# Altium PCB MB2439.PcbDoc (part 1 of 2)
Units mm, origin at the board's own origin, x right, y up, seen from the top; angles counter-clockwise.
Board outline 43.1 x 47.12 mm, 4 copper layers (Top Layer, Internal 2, Internal 3, Bottom Layer), stack 1.565 mm thick; 79 components, 62 nets, 323 pads, 761 vias.
Unrouted connection lines stored in the file: 15.
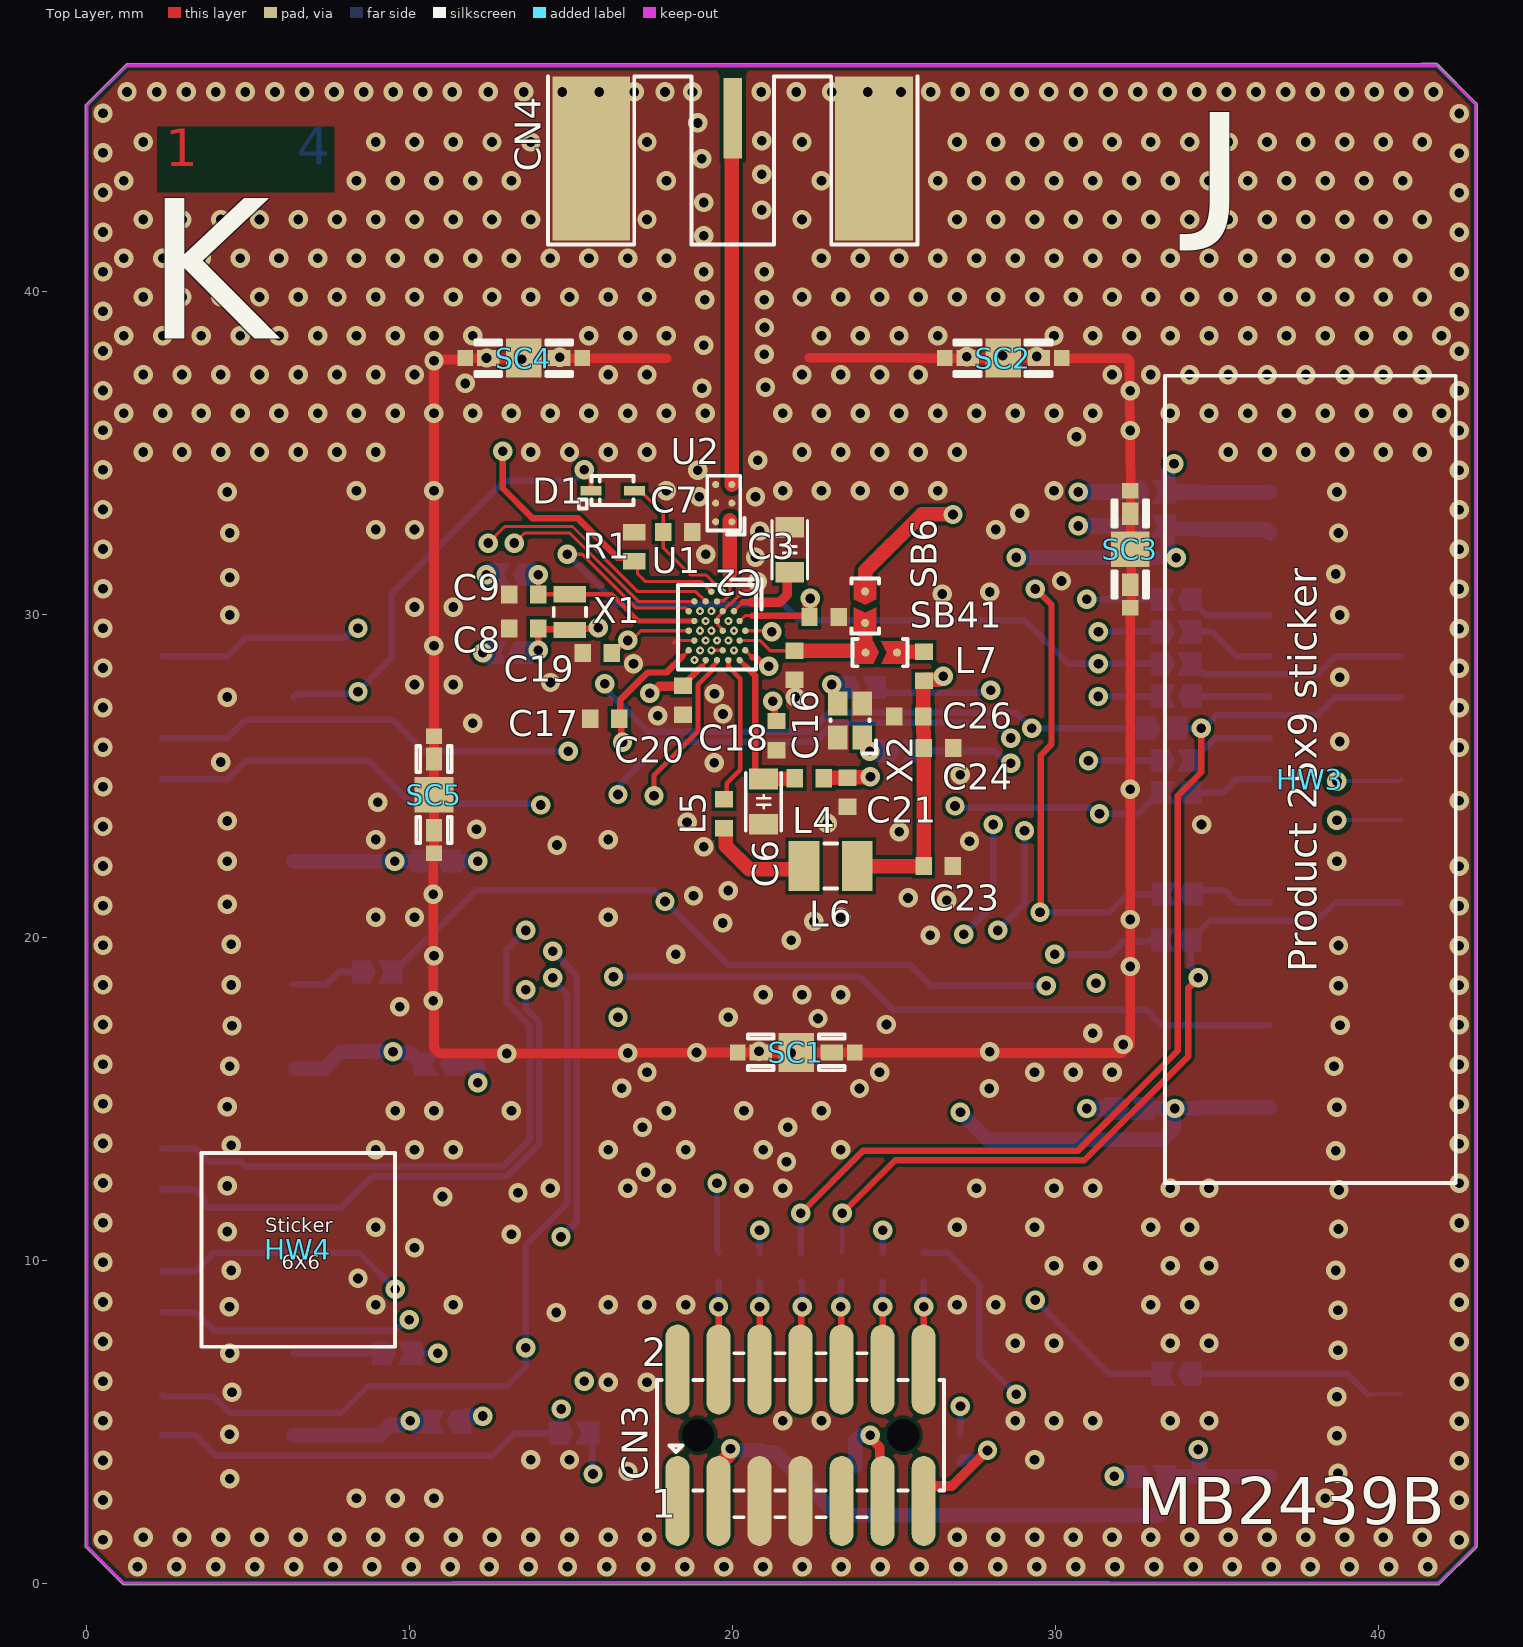
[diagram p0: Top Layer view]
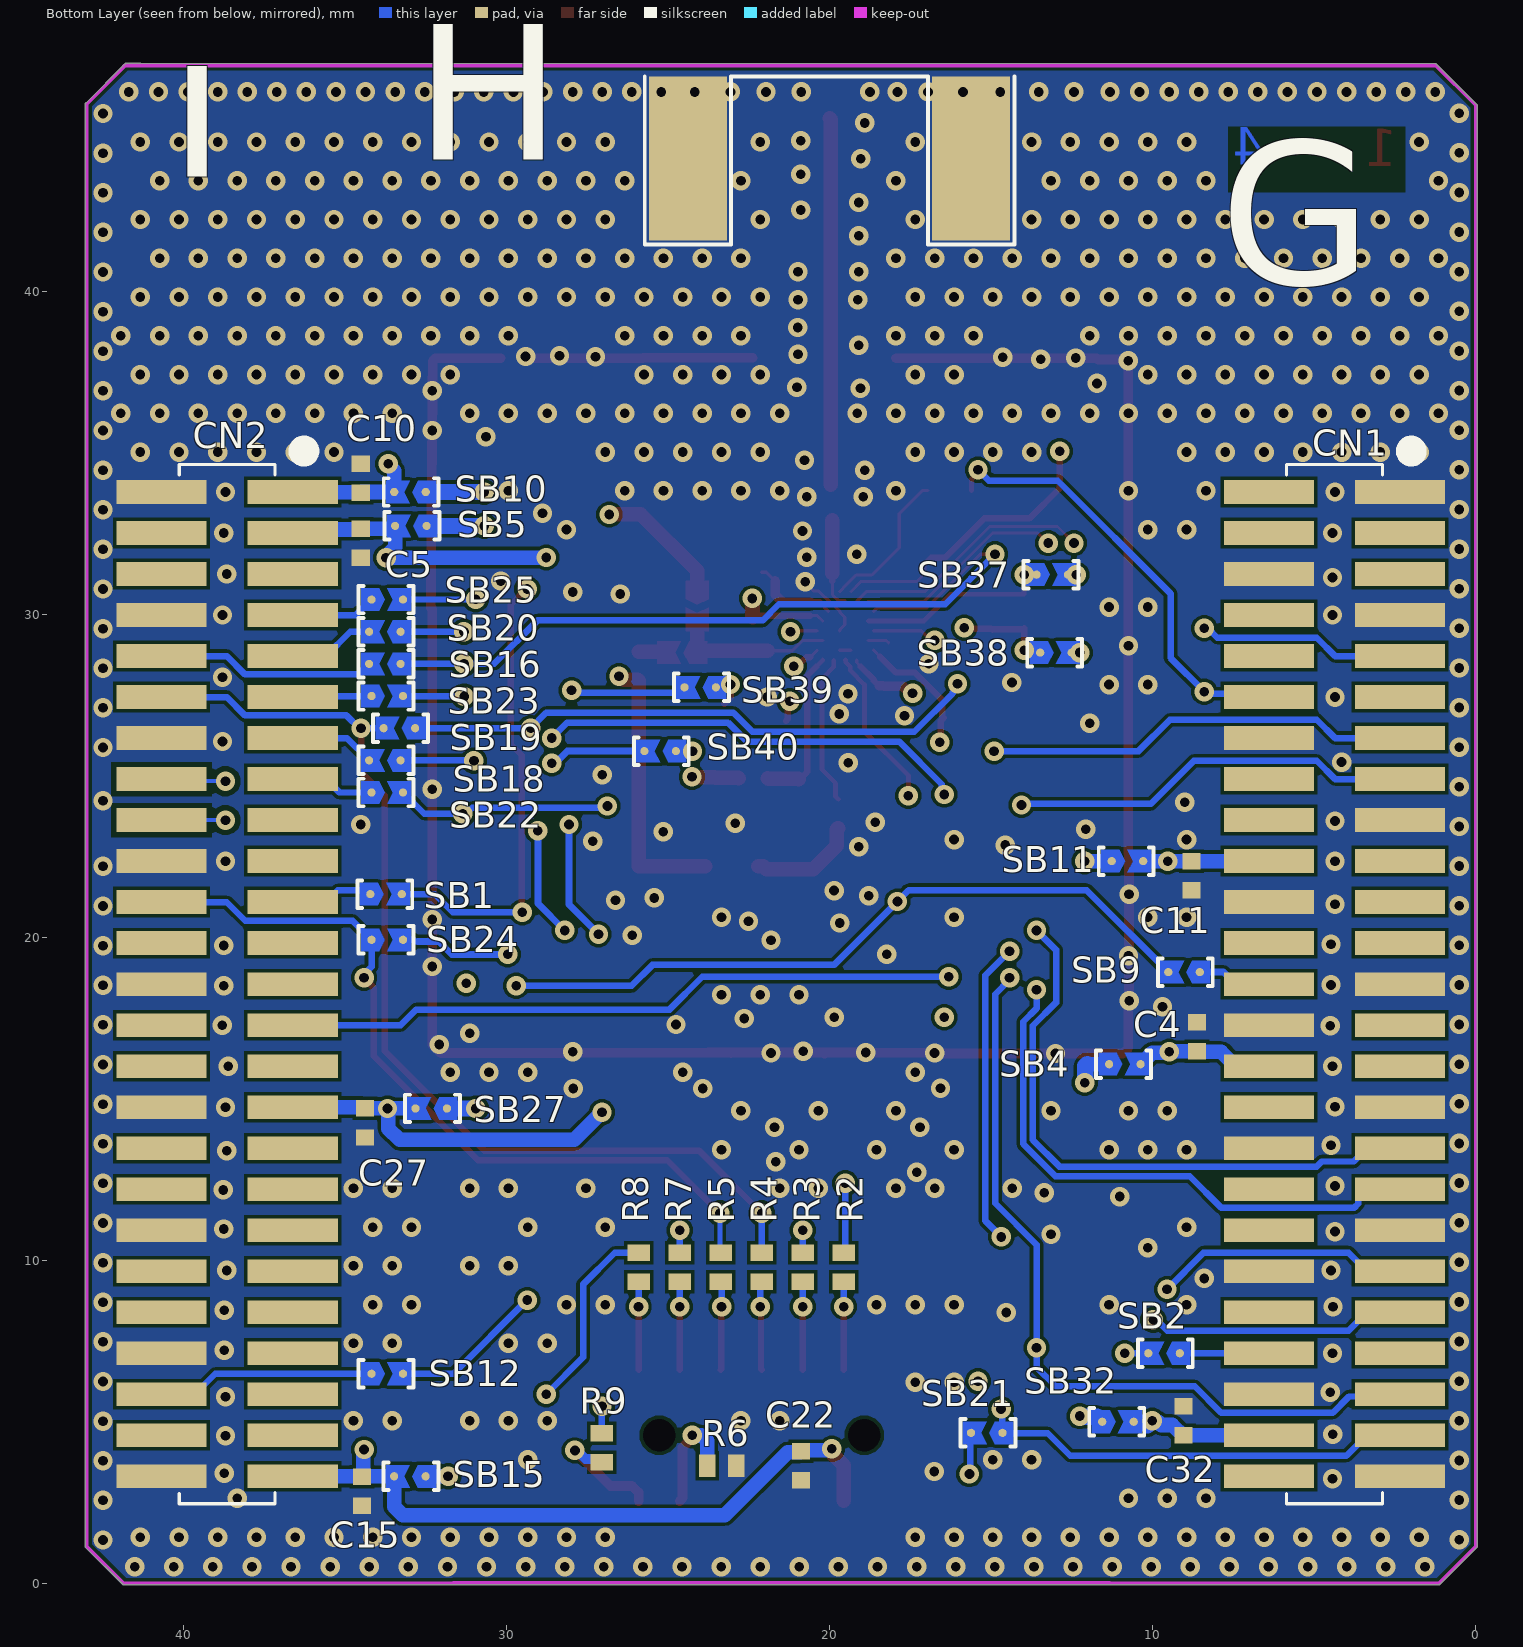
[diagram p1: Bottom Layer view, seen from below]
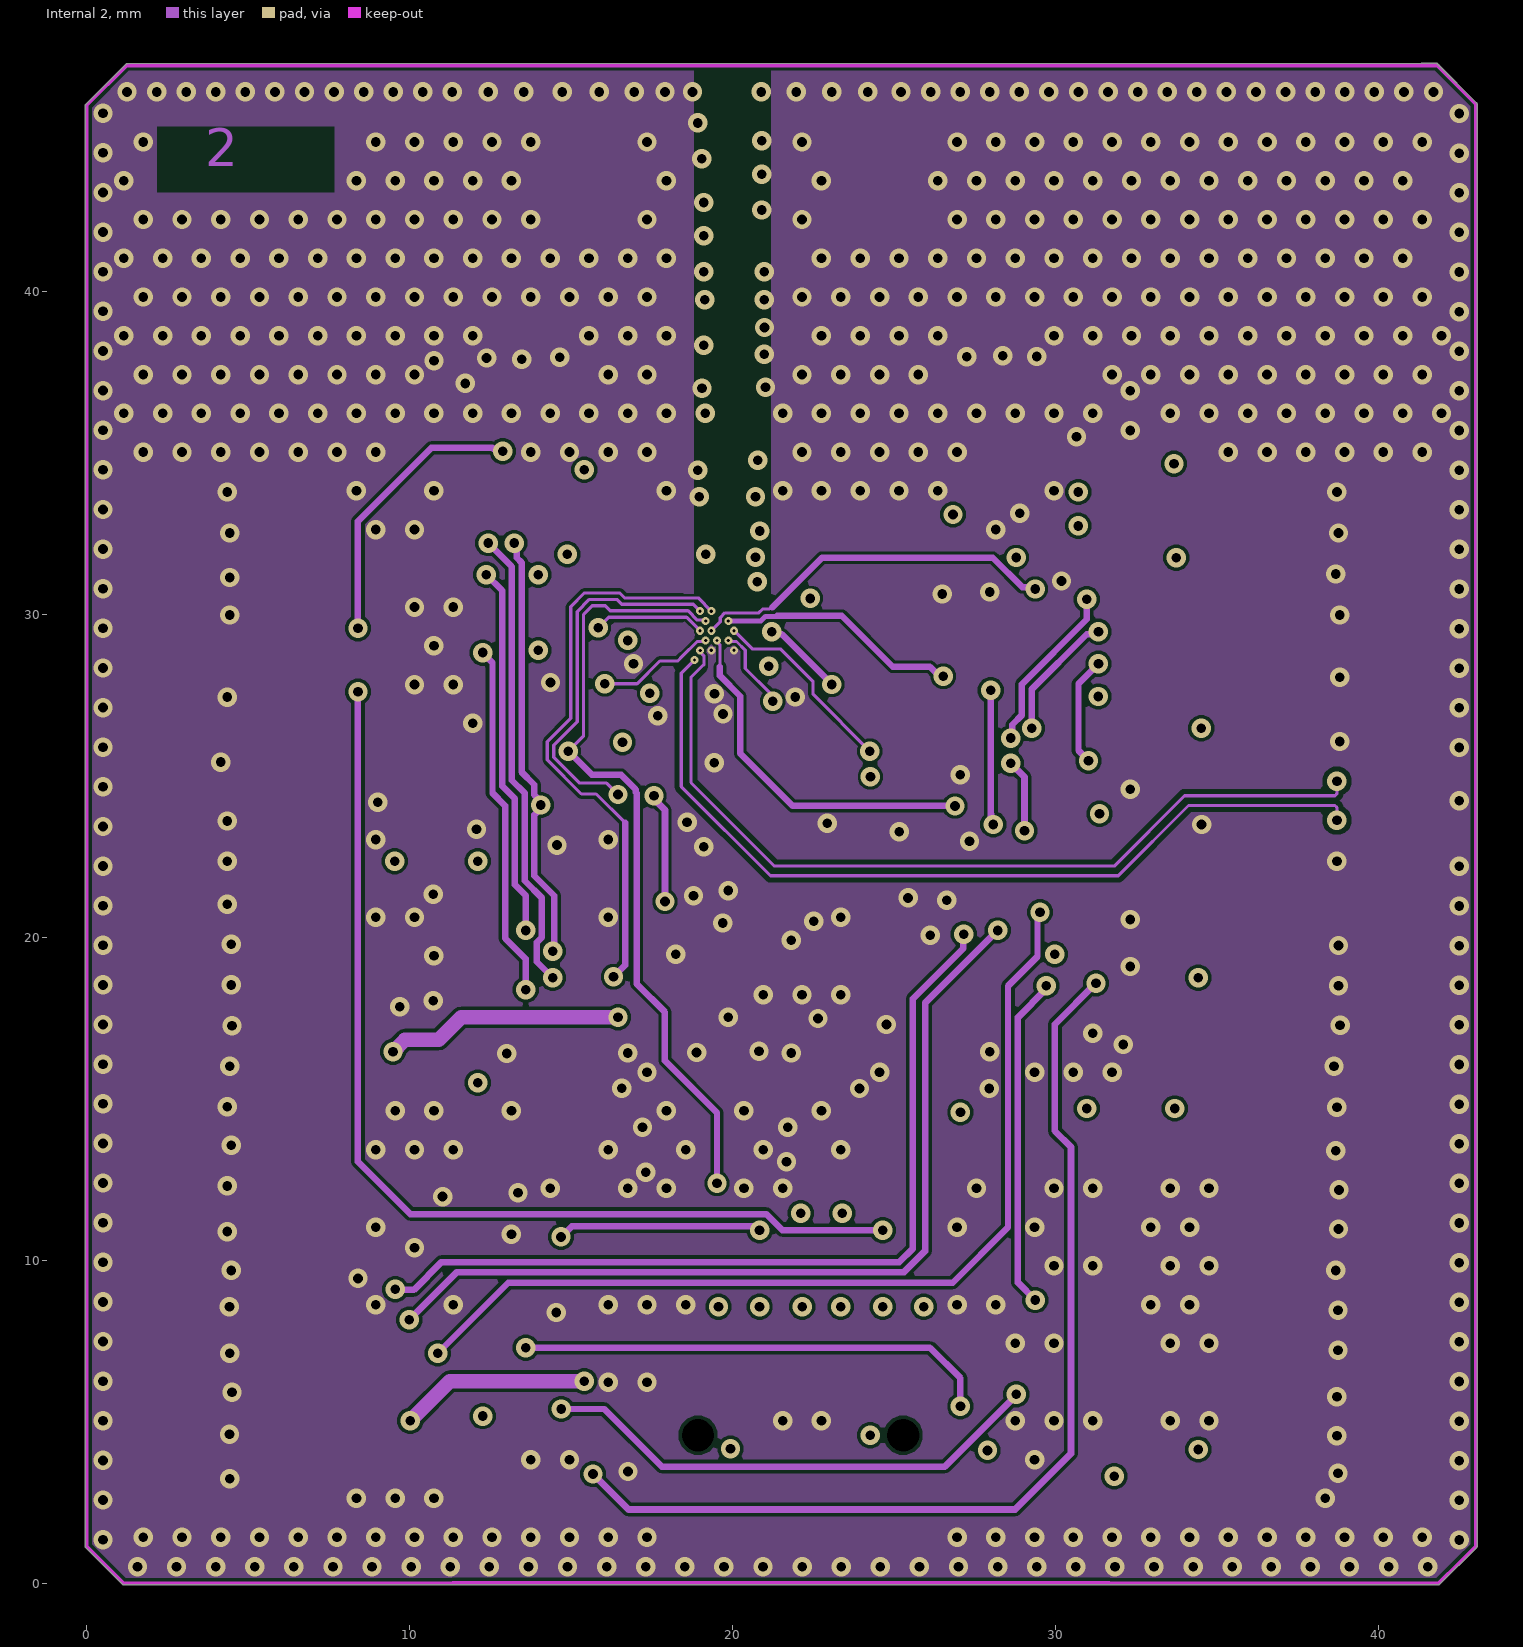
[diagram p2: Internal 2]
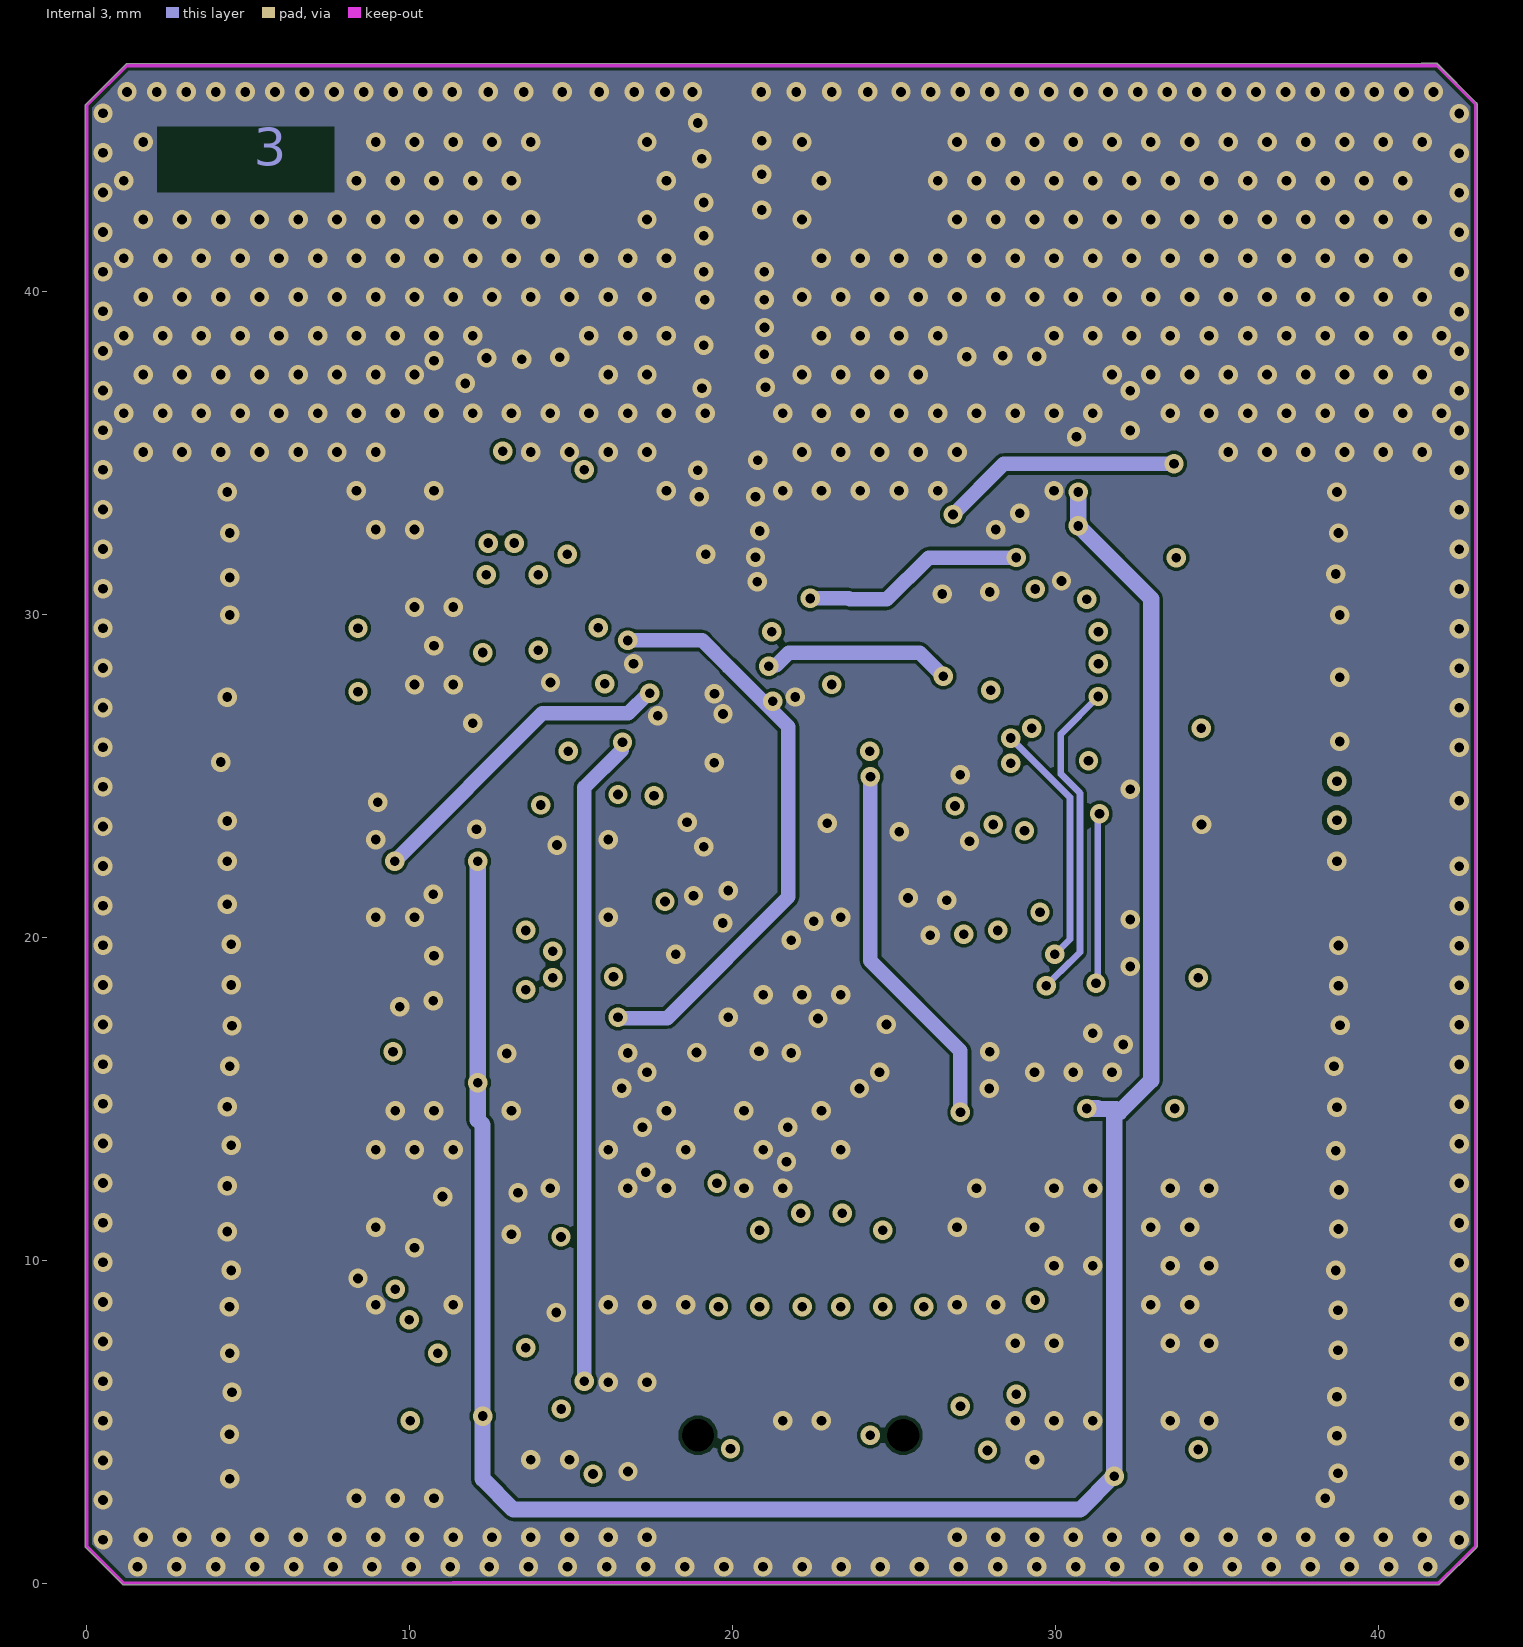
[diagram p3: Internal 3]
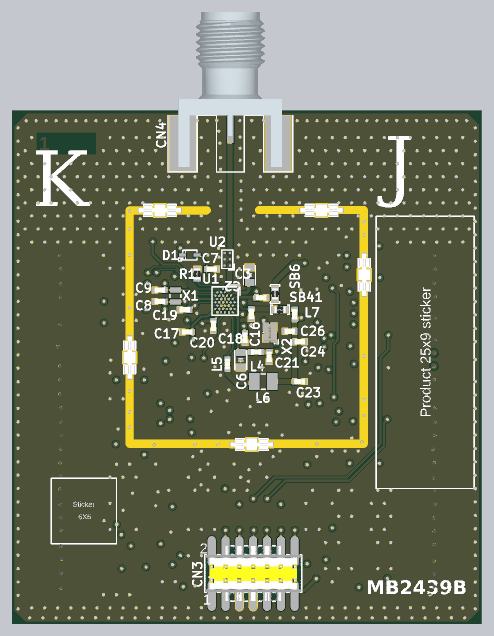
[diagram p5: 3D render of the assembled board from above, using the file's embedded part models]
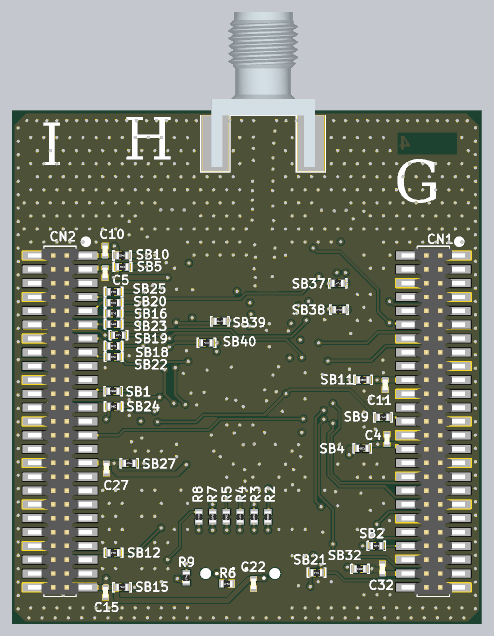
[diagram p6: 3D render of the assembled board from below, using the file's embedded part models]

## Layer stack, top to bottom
Top Solder: solder mask 0.0178, Solder Resist, Dk 4.2
Top Layer: signal copper 0.0406
Dielectric 1-2: core 0.0762, Prepreg, Dk 3.7
Internal 2: signal copper 0.0305
Dielectric 3: prepreg 1.27, Dk 4.5
Internal 3: signal copper 0.0305
Dielectric 3-4: core 0.0762, Prepreg, Dk 3.7
Bottom Layer: signal copper 0.0406
Board Layer Stack Bottom Solder: solder mask 0.0178, Solder Resist, Dk 4.2

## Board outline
-0.036,1.103 cw(c0,1.139) -0.05,1.139 -0.05,45.75 -0.05,45.755 cw(c0,45.755) -0.035,45.791 1.209,47.036 cw(c1.245,47) 1.245,47.05 41.326,47.066 41.78,47.066 cw(c41.78,47.015) 41.816,47.051 43.03,45.837 cw(c43.001,45.795) 43.051,45.795 cw(c43.002,45.795) 43.05,45.785 43.05,1.151 cw(c43.002,1.141) 43.051,1.141 cw(c43.001,1.141) 43.037,1.105 41.888,-0.036 cw(c41.852,0) 41.852,-0.05 1.139,-0.05 cw(c1.139,0) 1.103,-0.036

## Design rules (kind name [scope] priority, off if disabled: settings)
Clearance Clearance_CSP [WithinRoom('CSP')] p1: gap=0.075 ignorepadtopadclearanceinfootprint=FALSE
Clearance Clearance_DIFF90 [InNetClass('DIFF90')] p2: gap=0.16 ignorepadtopadclearanceinfootprint=FALSE
Clearance Clearance_IPD [WithinRoom('IPD')] p3: gap=0.1 ignorepadtopadclearanceinfootprint=FALSE
Clearance Clearance_RF [InNetClass('RF')] p4: gap=0.127 ignorepadtopadclearanceinfootprint=FALSE
Clearance [All] p5: gap=0.1 ignorepadtopadclearanceinfootprint=FALSE
ComponentClearance [All] p1: gap=0.1 collisioncheckmode=3 verticalgap=0.1 showdistances=FALSE
DiffPairsRouting [All] p1: maxlimit=0.2 minlimit=0.127 mostfreqgap=0.2 toplayer_mingap=0.2 toplayer_minwidth=0.1 toplayer_maxwidth=0.11 toplayer_prefwidth=0.11 midlayer1_mingap=0.2 midlayer1_minwidth=0.1 midlayer1_maxwidth=0.1 midlayer1_prefwidth=0.1 midlayer4_maxgap=0.127 midlayer4_prefgap=0.127 midlayer4_minwidth=0.05 midlayer4_maxwidth=0.14 midlayer4_prefwidth=0.072 bottomlayer_maxgap=0.127 bottomlayer_prefgap=0.127 bottomlayer_minwidth=0.127 bottomlayer_maxwidth=0.127 bottomlayer_prefwidth=0.127 impedanceprofiledriven=TRUE impedanceprofileid={FC601ECF-E89B-4FE3-84EC-BC5082A28B8A} impedanceprofilevalue=90.000000 maxuncoupledlength=12.7
HoleSize [All] p1: absolutevalues=TRUE maxlimit=10 minlimit=0.025 maxpercent=80.000 minpercent=20.000
HoleToHoleClearance [All] p1: gap=0.2 allowstackedmicrovias=TRUE
MatchedLengths "Schematic Matched Net Lengths" [InNetClass('DIFF90')] p1: tolerance=2 checknetsindiffpair=TRUE checkdiffpairvsdiffpair=FALSE checkxsignals=FALSE checkothers=FALSE
MaxMinImpedance "Schematic Impedance Constraint" [InNetClass('DIFF90')] p1: minimum=80.00 maximum=100.0
MinimumSolderMaskSliver [All] p1: minsoldermaskwidth=0.06
PlaneConnect [All] p1: planeconnectstyle=Relief reliefexpansion=0.508 reliefentries=4 reliefconductorwidth=0.21 reliefairgap=0.21
PolygonConnect PolygonConnect_1 [All vs IsNamedPolygon('GND_L01_P000')] p1: connectstyle=Direct reliefconductorwidth=0.254 reliefentries=4 polygonreliefangle="90 Angle" airgapwidth=0.254
PolygonConnect [All vs IsNamedPolygon('GND_L01_P000')] p2: connectstyle=Direct reliefconductorwidth=0.254 reliefentries=4 polygonreliefangle="90 Angle" airgapwidth=0.254
PolygonConnect Path_RF [InNet('NetC12_2')] p3: connectstyle=Direct reliefconductorwidth=0.254 reliefentries=4 polygonreliefangle="90 Angle" airgapwidth=0.254
PolygonConnect PolygonConnect_via [IsVia] p4: connectstyle=Direct reliefconductorwidth=0.254 reliefentries=4 polygonreliefangle="90 Angle" airgapwidth=0.254
PolygonConnect General [All] p5: connectstyle=Direct reliefconductorwidth=0.2 reliefentries=4 polygonreliefangle="90 Angle" airgapwidth=0.2
RoomDefinition IPD [False] p1: confinementstyle=ConfineIn formatcopy=TRUE lockcomponents=FALSE outline 19.338,34.239 20.416,34.239 20.416,32.754 19.338,32.754
RoomDefinition CSP [False] p2: confinementstyle=ConfineIn formatcopy=TRUE lockcomponents=FALSE outline 18.44,30.912 20.599,30.912 20.599,28.379 18.44,28.379
RoutingVias [All] p1: holewidth=0.3 width=0.8 viastyle="Through Hole" minholewidth=0.2 minwidth=0.5 maxholewidth=3.5 maxwidth=6.5
SilkToSilkClearance [All] p1: silktosilkclearance=0.2
SilkToSolderMaskClearance [IsPad] p1: minsilkscreentomaskgap=0.1 clearancetoexposedcopper=TRUE
SolderMaskExpansion [All] p1: expansion=0.102 istentingtop=FALSE
SupplyNets "Schematic Supply Nets_7" [InNet('VDD10')] p1: voltage=0.000
SupplyNets "Schematic Supply Nets_6" [InNet('VDD8')] p2: voltage=0.000
SupplyNets "Schematic Supply Nets_5" [InNet('GND')] p3: voltage=0.000
SupplyNets "Schematic Supply Nets_4" [InNet('VDD15')] p4: voltage=0.000
SupplyNets "Schematic Supply Nets_3" [InNet('VDDA')] p5: voltage=0.000
SupplyNets "Schematic Supply Nets_2" [InNet('VDD9')] p6: voltage=0.000
SupplyNets "Schematic Supply Nets_1" [InNet('VDD5')] p7: voltage=0.000
SupplyNets "Schematic Supply Nets" [InNet('VDD4')] p8: voltage=0.000
Width [All] p1: maxlimit=6 minlimit=0.1 preferedwidth=0.254 toplayer_prefwidth=0.15 midlayer1_maxwidth=0.512 midlayer1_prefwidth=0.15 midlayer4_minwidth=0.21 midlayer4_maxwidth=0.512 bottomlayer_prefwidth=0.15 minimp=50.000000 maximp=50.000000 favimp=50.000000
22 further rules are at their usual default settings.

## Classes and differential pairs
net class DIFF90: USB_FS_N USB_FS_P
differential pair class DIFF90: USB_FS
net class RF: NetCN4_1 NetU1_F2
component class "STM32 microcontroller I/Os & Clock": C4 C5 C7 C8 C9 C10 C11 C15 C27 C32 CN1 CN2 D1 R1 SB1 SB2 SB4 SB5 SB9 SB10 SB11 SB12 SB15 SB16 SB18 SB19 SB20 SB21 SB22 SB23 SB24 SB25 SB27 SB32 SB37 SB38 SB39 SB40 U1 X1 X2
component class "RF & Power Management Schematic": C2 C3 C6 C16 C17 C18 C19 C20 C21 C22 C23 C24 C26 CN3 CN4 HW1 L4 L5 L6 L7 R2 R3 R4 R5 R6 R7 R8 R9 SB6 SB41 SC1 SC2 SC3 SC4 SC5 U2
component class Project_Overview: HW2 HW3 HW4
differential pair USB_FS: +USB_FS_P -USB_FS_N

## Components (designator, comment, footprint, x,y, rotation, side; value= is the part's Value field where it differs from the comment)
C2 "Capacitor" C0603_H0P8 21.769,32.001 r270 top value=470nF
C3 "Capacitor" C0402 22.827,29.914 r0 top value=100nF
C4 "Capacitor" C0402 8.627,16.919 r270 bottom value=1uF
C5 "Capacitor" C0402 34.519,32.207 r90 bottom value=1uF
C6 "Capacitor" C0603_H0P8 20.955,24.2 r270 top value=10uF
C7 "Capacitor" C0402 18.297,32.546 r180 top value=100nF
C8 "Capacitor" C0402 13.529,29.567 r0 top value=6pF
C9 "Capacitor" C0402 13.529,30.62 r0 top value=6pF
C10 "Capacitor" C0402 34.519,34.211 r270 bottom value=1uF
C11 "Capacitor" C0402 8.788,21.907 r90 bottom value=1uF
C15 "Capacitor" C0402 34.478,2.845 r90 bottom value=1uF
C16 "Capacitor" C0402 21.919,28.425 r90 top value=100nF
C17 "Capacitor" C0402 16.039,26.766 r180 top value=100nF
C18 "Capacitor" C0402 21.351,26.247 r270 top value=100nF
C19 "Capacitor" C0402 15.811,28.804 r180 top value=100nF
C20 "Capacitor" C0402 18.455,27.337 r90 top value=1uF
C21 "Capacitor" C0402 23.559,24.496 r270 top value=1uF
C22 "Capacitor" C0402 20.887,3.631 r270 bottom value=1uF
C23 "Capacitor" C0402 26.359,22.205 r180 top value=4.7uF
C24 "Capacitor" C0402 26.372,25.864 r0 top value=100nF
C26 "Capacitor" C0402 25.455,26.834 r180 top value=100nF
C27 "Capacitor" C0402 34.392,14.249 r90 bottom value=1uF
C32 "Capacitor" C0402 9.044,5.027 r270 bottom value=1uF
CN1 "Header 25x2" FTSH-125-02-L-DV 4.366,18.548 r180 bottom locked
CN2 "Header 25x2" FTSH-125-02-L-DV 38.656,18.548 r180 bottom locked
CN3 "Header 7x2" CON_SAMTEC_FTSH-107-01-L-DV-K-A 22.101,4.579 r0 top locked
CN4 "SMA-J-P-H-ST-EM1" CON_SMA-RF_CINCH_142-0701-851 20,46.65 r0 top value=Jack_SMA_142-0701-851
D1 "SCHOTTKY_1A_2K" DIO_SOD523_1A_2K 16.281,33.831 r180 top value=BAT54KFILM
HW1 "Shield Cover" SHIELD_WURTH_36003200_21P8X21P8 90.373,17.78 r0 top value=36003200
HW3 "STICKER_PRODUCT" STICKER_PRODUCT_25X9 37.889,24.889 r90 top value="Sticker Product"
HW4 "STICKER_ES" STICKER_ES_6X6 6.547,10.321 r0 top value=N/A
L4 "BEAD" C0402 22.369,24.925 r180 top value="33R @ 100MHz"
L5 "Inductor" C0402 19.728,23.825 r270 top value=10nH
L6 "Inductor" IND_0805_MURATA_LQM21_H1P0 23.034,22.205 r0 top value=2.2uH
L7 "BEAD" C0402 25.917,28.395 r270 top value="33R @ 100MHz"
R1 "Resistor" R0402 16.954,32.096 r90 top value=100K
R2 "Resistor" R0402 19.561,9.779 r90 bottom value=47R
R3 "Resistor" R0402 20.832,9.779 r90 bottom value=47R
R4 "Resistor" R0402 22.103,9.779 r90 bottom value=47R
R5 "Resistor" R0402 23.374,9.779 r90 bottom value=47R
R6 "Resistor" R0402 23.345,3.631 r0 bottom value=47R
R7 "Resistor" R0402 24.646,9.779 r90 bottom value=47R
R8 "Resistor" R0402 25.917,9.779 r90 bottom value=47R
R9 "Resistor" R0402 27.051,4.191 r270 bottom value=47R
SB1 "SB_ON" SOLDER-BRIDGE_R0402-0R 33.773,21.336 r180 bottom
SB2 "SB_ON" SOLDER-BRIDGE_R0402-0R 9.606,7.118 r0 bottom
SB4 "SB_ON" SOLDER-BRIDGE_R0402-0R 10.897,16.07 r180 bottom
SB5 "SB_ON" SOLDER-BRIDGE_R0402-0R 32.931,32.738 r0 bottom
SB6 "SB_ON" SOLDER-BRIDGE_R0402-0R 24.101,30.259 r270 top
SB9 "SB_ON" SOLDER-BRIDGE_R0402-0R 8.988,18.921 r0 bottom
SB10 "SB_ON" SOLDER-BRIDGE_R0402-0R 32.959,33.788 r0 bottom
SB11 "SB_ON" SOLDER-BRIDGE_R0402-0R 10.816,22.358 r180 bottom
SB12 "SB_ON" SOLDER-BRIDGE_R0402-0R 33.736,6.483 r180 bottom
SB15 "SB_ON" SOLDER-BRIDGE_R0402-0R 32.961,3.308 r0 bottom
SB16 "SB_ON" SOLDER-BRIDGE_R0402-0R 33.736,28.466 r0 bottom
SB18 "SB_ON" SOLDER-BRIDGE_R0402-0R 33.736,25.479 r0 bottom
SB19 "SB_ON" SOLDER-BRIDGE_R0402-0R 33.286,26.474 r0 bottom
SB20 "SB_ON" SOLDER-BRIDGE_R0402-0R 33.736,29.461 r0 bottom
SB21 "SB_ON" SOLDER-BRIDGE_R0402-0R 15.097,4.654 r0 bottom
SB22 "SB_ON" SOLDER-BRIDGE_R0402-0R 33.736,24.483 r180 bottom
SB23 "SB_ON" SOLDER-BRIDGE_R0402-0R 33.736,27.47 r180 bottom
SB24 "SB_ON" SOLDER-BRIDGE_R0402-0R 33.736,19.921 r180 bottom
SB25 "SB_ON" SOLDER-BRIDGE_R0402-0R 33.736,30.457 r180 bottom
SB27 "SB_ON" SOLDER-BRIDGE_R0402-0R 32.3,14.699 r0 bottom
SB32 "SB_ON" SOLDER-BRIDGE_R0402-0R 11.109,4.998 r180 bottom
SB37 "SB_ON" SOLDER-BRIDGE_R0402-0R 13.143,31.228 r180 bottom
SB38 "SB_ON" SOLDER-BRIDGE_R0402-0R 13.03,28.816 r180 bottom
SB39 "SB_ON" SOLDER-BRIDGE_R0402-0R 23.971,27.74 r0 bottom
SB40 "SB_ON" SOLDER-BRIDGE_R0402-0R 25.211,25.765 r0 bottom
SB41 "SB_ON" SOLDER-BRIDGE_R0402-0R 24.563,28.816 r0 top
SC1 "Shield-clip_S0951-46R" CLIP_HARWIN_S0951-46R 21.968,16.434 r180 top locked value=S0951-46R
SC2 "Shield-clip_S0951-46R" CLIP_HARWIN_S0951-46R 28.372,37.934 r180 top locked value=S0951-46R
SC3 "Shield-clip_S0951-46R" CLIP_HARWIN_S0951-46R 32.309,32.021 r90 top locked value=S0951-46R
SC4 "Shield-clip_S0951-46R" CLIP_HARWIN_S0951-46R 13.529,37.934 r180 top locked value=S0951-46R
SC5 "Shield-clip_S0951-46R" CLIP_HARWIN_S0951-46R 10.75,24.42 r90 top locked value=S0951-46R
U1 "STM32WBA25HEF7" ICC_WLCSP37_2P61X2P41_P035 18.085,28.045 r0 top locked
U2 "IC_MLPF-WB-05D3" ICC_CSPG_6BUMPS_1X1P60_P050-P0577 19.722,33.443 r180 top value=MLPF-WB-05D3
X1 "XTAL_2_PINS" CRY_NX1610SE_2P 14.958,30.07 r270 top value=32.768kHz
X2 "XTAL_4_PINS" CRY_NX1612SA_4P 23.632,26.713 r90 top value=32MHz

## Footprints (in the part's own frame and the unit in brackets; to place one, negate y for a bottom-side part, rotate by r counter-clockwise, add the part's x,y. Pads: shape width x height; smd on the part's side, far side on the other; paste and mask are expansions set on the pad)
C0402 [mm]
  rect 0.51x0.56 smd mask+0.05: 1(-0.45,0) 2(0.45,0)
  body extent -0.5,-0.3 0.5,0.3, height 0.4
C0603_H0P8 [mm]
  rect 0.64x0.89 smd mask+0.05: 1(-0.7,0) 2(0.7,0)
  silkscreen extent -0.9,-0.55 0.9,0.55, body extent -0.9,-0.5 0.9,0.5, height 1
CLIP_HARWIN_S0951-46R [mm] "MCD-01587_CLIP-X1"
  rect 0.48x0.5 smd mask+0.1: 1(-1.81,0) 1(1.81,0)
  rect 0.7x0.5 smd mask+0.1: 1(-1.1,0) 1(1.1,0)
  rect 1.1x1.2 smd mask+0.1: 1(0,0)
  silkscreen extent -1.5,-0.55 1.5,0.55, body extent -2.05,-0.65 2.05,0.65, height 1.28
CON_SAMTEC_FTSH-107-01-L-DV-K-A [mm] "MCD-01959"
  oval 0.74x2.79 smd mask+0.05: 1(-3.81,-2.035) 2(-3.81,2.035) 3(-2.54,-2.035) 4(-2.54,2.035) 5(-1.27,-2.035) 6(-1.27,2.035) 7(0,-2.035) 8(0,2.035) 9(1.27,-2.035) 10(1.27,2.035) 11(2.54,-2.035) 12(2.54,2.035) 13(3.81,-2.035) 14(3.81,2.035)
  round 0 hole 1 unplated paste-2539.97 mask+0.05: NPTH1(-3.175,0) NPTH2(3.175,0)
  silkscreen extent -4.44,-2.54 4.44,2.54, body extent -4.44,-2.92 4.45,2.92, height 6.12
CON_SMA-RF_CINCH_142-0701-851 [mil] "MCD-02072"
  rect 22.83x98.43 smd mask+1.97: 1(0,-50.79)
  rect 95x200 smd mask+1.97: 2(172.48,-100) 3(-172.48,-100)
  rect 95x200 smd far side mask+1.97: 4(-172.48,-100) 5(172.48,-100)
  silkscreen extent -225,-205 225,0, body extent -189,-187 189,376, height 161
CRY_NX1610SE_2P [mm] "MCD-02291"
  rect 0.5x1 smd mask+0.05: 1(-0.55,0) 2(0.55,0)
  silkscreen extent -0.13,-0.5 0.13,0.5, body extent -0.8,-0.5 0.8,0.5, height 0.45
CRY_NX1612SA_4P [mm]
  rect 0.75x0.6 smd mask+0.038: 1(-0.525,-0.375) 2(0.525,-0.375) 3(0.525,0.375) 4(-0.525,0.375)
  silkscreen extent -1.02,-0.8 0.03,0.6, body extent -0.8,-0.6 0.8,0.6, height 0.51
DIO_SOD523_1A_2K [mm] "MCD-01677"
  rect 0.65x0.3 smd mask+0.05: 1(-0.675,0) 2(0.675,0)
  silkscreen extent -0.65,-0.45 1.05,0.55, body extent -0.85,-0.45 0.85,0.45, height 0.71
FTSH-125-02-L-DV [mil] "Header2x25 Reverse 1.27mm SAMTEC (FTSH-125-02-L-DV)"
  rect 110x29.02 smd: 1(80,600) 2(-80,600) 3(80,550) 4(-80,550) 5(80,500) 6(-80,500) 7(80,450) 8(-80,450) 9(80,400) 10(-80,400) 11(80,350) 12(-80,350) 13(80,300) 14(-80,300) 15(80,250) 16(-80,250) 17(80,200) 18(-80,200) 19(80,150) 20(-80,150) 21(80,100) 22(-80,100) 23(80,50) 24(-80,50) 25(80,0) 26(-80,0) 27(80,-50) 28(-80,-50) 29(80,-100) 30(-80,-100) 31(80,-150) 32(-80,-150) 33(80,-200) 34(-80,-200) 35(80,-250) 36(-80,-250) 37(80,-300) 38(-80,-300) 39(80,-350) 40(-80,-350) 41(80,-400) 42(-80,-400) 43(80,-450) 44(-80,-450) 45(80,-500) 46(-80,-500) 47(80,-550) 48(-80,-550) 49(80,-600) 50(-80,-600)
  silkscreen extent -58,-633 103,659, body extent -115,-625 115,625, height 190
ICC_CSPG_6BUMPS_1X1P60_P050-P0577 [mm] "MCD-03490"
  round 0.22 smd paste+0 mask+0: A1(-0.25,0.577) A2(-0.25,0) A3(-0.25,-0.577) B1(0.25,0.577) B2(0.25,0) B3(0.25,-0.577)
  silkscreen extent -0.64,-0.85 0.51,0.97, body extent -0.51,-0.81 0.51,0.81, height 0.7
ICC_WLCSP37_2P61X2P41_P035 [mm]
  round 0.2 smd paste+0 mask+0.038: A5(2.303,1.446) A7(2.303,0.84) B4(2.128,1.749) B6(2.128,1.143) B8(2.128,0.537) C3(1.953,2.052) C5(1.953,1.446) C7(1.953,0.84) D4(1.778,1.749) D6(1.778,1.143) D8(1.778,0.537) E1(1.603,2.658) E3(1.603,2.052) E5(1.603,1.446) E7(1.603,0.84) F2(1.428,2.355) F4(1.428,1.749) F6(1.428,1.143) F8(1.428,0.537) G1(1.253,2.658) G3(1.253,2.052) G5(1.253,1.446) G7(1.253,0.84) H2(1.078,2.355) H4(1.078,1.749) H6(1.078,1.143) H8(1.078,0.537) J3(0.903,2.052) J5(0.903,1.446) J7(0.903,0.84) K2(0.728,2.355) K4(0.728,1.749) K6(0.728,1.143) K8(0.728,0.537) L3(0.553,2.052) L5(0.553,1.446) L7(0.553,0.84)
  silkscreen extent 0.22,0.25 2.8,3.03, body extent 0.22,0.25 2.63,2.86, height 0.5
IND_0805_MURATA_LQM21_H1P0 [mm] "MCD-04691"
  rect 0.95x1.55 smd mask+0.05: 1(-0.825,0) 2(0.825,0)
  silkscreen extent -0.2,-0.7 0.2,0.7, body extent -1.07,-0.7 1.07,0.7, height 1
R0402 [mm]
  rect 0.51x0.7 smd mask+0.05: 1(-0.45,0) 2(0.45,0)
  body extent -0.52,-0.3 0.52,0.3, height 0.4
SHIELD_WURTH_36003200_21P8X21P8 [mm] "MCD-04686"
  silkscreen extent -10.95,-10.95 10.95,10.95, body extent -10.9,-10.9 10.9,10.9, height 2.3
SOLDER-BRIDGE_R0402-0R [mil] "MCD-01619"
  round 10 smd paste-393.7: 1(-17.72,0) 2(20.67,0)
  Top Layer region: 1.48,13.78 8.37,0 1.48,-13.78 30.51,-13.78 30.51,13.78
  Top Layer region: -30.51,-13.78 -30.51,13.78 -8.37,13.78 -1.48,0 -8.37,-13.78
  silkscreen extent -33,-17 33,17, body extent -20,-12 20,12, height 14
STICKER_ES_6X6 [mm] "Sticker to mention board QR code 8X8"
  silkscreen extent -3,-3 3,3
STICKER_PRODUCT_25X9 [mm] "Sticker to mention board CPN code"
  silkscreen extent -12.5,-4.5 12.5,4.5

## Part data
C2: library part MCD-01006, "Capacitor, MLCC, 470nF, 16V, X7R, +/-10%, 0603, T=0.8mm", Manufacturer=YAGEO, Manufacturer_Part_Number=CC0603KRX7R7BB474, Package=0603
C3 C7 C16 C17 C18 C19 C24 C26: library part MCD-00006, "Capacitor, MLCC, 100nF, 16V, X7R, +/-10%, 0402, T=0.5mm", Manufacturer=YAGEO, Manufacturer_Part_Number=CC0402KRX7R7BB104, Package=0402
C4 C5 C10 C11 C15 C20 C21 C22 C27 C32: library part MCD-01722, "Capacitor, MLCC, 1uF, 10V, X5R, +/-10%, 0402, T=0.5mm", Manufacturer=YAGEO, Manufacturer_Part_Number=CC0402KRX5R6BB105, Package=0402
C6: library part MCD-02733, "Capacitor, MLCC, 10uF, 10V, X6S, +/-20%, 0603, T=1mm", Manufacturer=MURATA, Manufacturer_Part_Number=GRM188C81A106MA73, Package=0603
C8 C9: library part MCD-03185, "Capacitor, MLCC, 6pF, 50V, C0G/NP0, +/-0,25pF, 0402, T=0.5mm", Manufacturer=MURATA, Manufacturer_Part_Number=GJM1555C1H6R0CB01, Package=0402
C23: library part MCD-01356, "Capacitor, MLCC, 4.7uF, 6V3, X5R, 20%, 0402, T=0.5mm", Manufacturer=MURATA, Manufacturer_Part_Number=GRM155R60J475ME47, Package=0402
CN1 CN2: library part MCD-02746, "Header, 25x2, 1.27mm, VR, SMD, T=4.83mm", Manufacturer=SAMTEC, Manufacturer_Part_Number=FTSH-125-02-L-DV
CN3: library part MCD-01531, "Header, 7x2, 1.27mm, VR, T=5.97mm, FTSH series STDC14 without Alignment Pin", Manufacturer=SAMTEC, Manufacturer_Part_Number=FTSH-107-01-L-DV-K
CN4: library part MCD-02072, "Jack_SMA, VR, PCB edge, 50R, T=7.92mm", Manufacturer=CINCH, Manufacturer_Part_Number=142-0701-851
D1: library part MCD-01677, "Diode, Schottky, 0V9, 100mA, 40V, SOD-523", Manufacturer=STMICROELECTRONICS, Manufacturer_HQ_COO=EU, Manufacturer_Part_Number=BAT54KFILM, Package=SOD-523
HW1: library part MCD-04686, "RF Shield cover, 21.5x21.5x3.3mm", Manufacturer="WURTH ELEKTRONIK", Manufacturer_Part_Number=36003200
HW3: library part MCD-00547, "Sticker product, 25x9mm", Manufacturer=N/A, Manufacturer_HQ_COO=Unknown
HW4: library part MCD-00234, "Sticker ES, 6x6mm", Manufacturer=N/A
L4 L7: library part MCD-04372, "Ferrite bead, 33R @ 100MHz, 3A, 22mR, 0402, T=0.5mm", Manufacturer=MURATA, Manufacturer_Part_Number=BLM15PX330SN1, Package=0402
L5: library part MCD-03035, "Inductor, 10nH, +/-2%, 0.5A, 260mR, 0402, T=0.5mm", Manufacturer=MURATA, Manufacturer_Part_Number=LQG15HS10NJ02D, Package=0402
L6: library part MCD-04691, "Inductor, 2.2uH, +/-30%, 0.6A, 0R23, 0805, T=0.9mm", Manufacturer=MURATA, Manufacturer_Part_Number=LQM21PN2R2NGC, Package=0805
R1: library part MCD-00059, "Resistor, 100K, 0402, +/-1%, 1/16W", Manufacturer=YAGEO, Manufacturer_Part_Number=RC0402FR-07100KL, Package=0402
R2 R3 R4 R5 R6 R7 R8 R9: library part MCD-00481, "Resistor, 47R, 0402, +/-1%, 1/16W", Manufacturer=YAGEO, Manufacturer_Part_Number=RC0402FR-0747RL, Package=0402
SB1 SB2 SB4 SB5 SB6 SB9 SB10 SB11 SB12 SB15 SB16 SB18 SB19 SB20 SB21 SB22 SB23 SB24 SB25 SB27 SB32 SB37 SB38 SB39 SB40 SB41: library part MCD-01618, "Resistor, 0R, SB0402, 5%, 0.063W", Manufacturer=YAGEO, Manufacturer_Part_Number=RC0402JR-070RL, Package=0402
SC1 SC2 SC3 SC4 SC5: library part MCD-01587, "shield clip Harwin S0951-46R to fix RF shielded cavity", Manufacturer=HARWIN, Manufacturer_Part_Number=S0951-46R
U1: library part MCD-04938, "MCU, ARM Cortex-M33 32-bit, 512KB Flash, 96KB RAM, Crypto", Manufacturer=STMICROELECTRONICS, Package=WLCSP37
U2: library part MCD-05125, "IC, 2.4GHz low pass filter matched to WBA CSP package mini board", Manufacturer=STMICROELECTRONICS, Manufacturer_Part_Number=MLPF-WB-05D3, Package=CSP6
X1: library part MCD-02579, "Crystal, 32.768kHz, 6pF, +/-20ppm, 70KR, 1.6x1mm", Manufacturer=NDK, Manufacturer_Part_Number=NX1610SE-32.768KHz-EXS00A-MU01501, Package=1.6x1.0mm
X2: library part MCD-02578, "Crystal, 32MHz, 8pF, +/-10ppm, 40R, 1612(metric)", Manufacturer=NDK, Manufacturer_Part_Number=NX1612SA-32MHz-EXS00A-CS09166, Package=1612(metric)

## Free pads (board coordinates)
  round 0.508 on Mech16: 1(-2.772,-77.554) 1(46.075,-77.554)

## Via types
v1: diameter 0.6, hole 0.3, Top Layer to Bottom Layer, tented both sides, 747 vias
v2: diameter 0.25, hole 0.1, Top Layer to Internal 2, 14 vias

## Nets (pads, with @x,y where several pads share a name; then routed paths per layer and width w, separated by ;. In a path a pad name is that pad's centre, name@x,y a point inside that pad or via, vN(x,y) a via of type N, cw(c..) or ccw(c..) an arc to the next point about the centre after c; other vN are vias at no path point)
GND: C2.1 C3.2 C4.1 C5.1 C6.2 C7.1 C8.1 C9.1 C10.1 C11.1 C15.1 C16.1 C17.2 C18.2 C19.2 C20.1 C21.2 C22.2 C23.1 C24.2 C26.2 C27.1 C32.1 CN1.1 CN1.6 CN1.7 CN1.14 CN1.17 CN1.22 CN1.25 CN1.28 CN1.31 CN1.34 CN1.37 CN1.40 CN1.46 CN1.49 CN2.2 CN2.8 CN2.14 CN2.20 CN2.26 CN2.32 CN2.38 CN2.44 CN2.50 CN3.5 CN3.7 CN4.2 CN4.3 CN4.4 CN4.5 R1.2 R6.1 SC1.1 SC2.1 SC3.1 SC4.1 SC5.1 U1.C7 U1.E3 U1.E5 U1.E7 U1.F4 U1.G7 U1.K6 U2.A2 U2.B1 U2.B2 U2.B3 X2.2 X2.4 | length 83.8
  Top Layer w0.1: 18.175,29.117 18.246,29.188 U1.K6@18.813,29.188 ; v2(19.338,28.885) U1.E7@19.688,28.885 ; U1.E5@19.688,29.491 19.688,29.518 19.532,29.674 19.532,29.775 U1.F4@19.513,29.794 19.532,29.813 19.532,29.914 19.688,30.07 U1.E3@19.688,30.097 19.913,30.322 19.937,30.322 20.335,30.72 20.492,30.72 20.599,30.827 20.605,30.833 20.605,30.844 v1@20.604,30.846
  Top Layer w0.3: v1(10.724,18.039) 10.75,18.013 10.75,16.576 10.926,16.4 16.733,16.4 v1(16.751,16.417) 16.759,16.426 18.856,16.426 18.864,16.417 18.88,16.434 20.124,16.434 20.158,16.4 20.192,16.434 SC1.1@20.868,16.434 20.885,16.417 20.902,16.434 SC1.1@21.816,16.434 ; v1@10.728,18.043 10.728,22.587 SC5.1@10.75,22.61 SC5.1@10.75,23.32 SC5.1@10.75,24.42 SC5.1@10.75,25.52 SC5.1@10.75,26.23 v1(10.75,37.853) 10.79,37.894 11.678,37.894 SC4.1@11.719,37.934 SC4.1@12.429,37.934 SC4.1@13.529,37.934 SC4.1@14.629,37.934 SC4.1@15.339,37.934 17.951,37.934 ; v1(21.816,16.417) 21.952,16.417 SC1.1@21.968,16.434 23.034,16.434 23.051,16.417 SC1.1@23.068,16.434 ; 22.377,37.948 25.781,37.948 25.795,37.934 SC2.1@26.562,37.934 SC2.1@27.272,37.934 SC2.1@28.372,37.934 SC2.1@29.472,37.934 ; SC1.1@23.068,16.434 SC1.1@23.778,16.434 23.786,16.426 28.255,16.426 28.263,16.417 32.045,16.417 32.309,16.681 v1(32.309,19.096) v1(32.309,24.583) 32.309,30.171 32.349,30.211 32.343,30.921 32.34,31.369 32.34,31.394 32.335,32.021 32.326,33.121 32.32,33.831 32.296,36.919 32.296,36.935 32.289,37.853 32.208,37.934 SC2.1@30.182,37.934
  other v1: 1.567,0.508 2.778,0.508 3.988,0.508 5.199,0.508 6.41,0.508 7.621,0.508 8.831,0.508 10.042,0.508 11.253,0.508 12.463,0.508 13.674,0.508 14.885,0.508 16.096,0.508 17.306,0.508 18.517,0.508 19.728,0.508 20.939,0.508 22.149,0.508 23.36,0.508 24.571,0.508 25.782,0.508 26.992,0.508 28.203,0.508 29.414,0.508 30.624,0.508 31.835,0.508 33.046,0.508 34.257,0.508 35.467,0.508 36.678,0.508 37.889,0.508 39.1,0.508 40.31,0.508 41.521,0.508 0.5,1.346 42.5,1.337 1.747,1.425 2.947,1.425 4.147,1.425 5.347,1.425 6.547,1.425 7.747,1.425 8.947,1.425 10.147,1.425 11.347,1.425 12.547,1.425 13.747,1.425 14.947,1.425 16.147,1.425 17.347,1.425 26.947,1.425 28.147,1.425 29.347,1.425 30.547,1.425 31.747,1.425 32.947,1.425 34.147,1.425 35.347,1.425 36.547,1.425 37.747,1.425 38.947,1.425 40.147,1.425 41.347,1.425 42.5,2.564 0.5,2.573 8.347,2.625 9.547,2.625 10.747,2.625 38.347,2.625 4.428,3.234 38.742,3.406 16.759,3.458 0.5,3.8 42.5,3.791 13.747,3.825 14.947,3.825 29.347,3.825 38.71,4.567 4.416,4.609 0.5,5.027 21.547,5.025 22.747,5.025 28.747,5.025 29.947,5.025 31.147,5.025 33.547,5.025 34.747,5.025 42.5,5.018 38.71,5.769 4.494,5.907 16.147,6.225 17.347,6.225 42.5,6.245 0.5,6.254 4.428,7.118 38.742,7.214 28.747,7.425 29.947,7.425 33.547,7.425 34.747,7.425 0.5,7.481 42.5,7.472 14.534,8.382 38.742,8.447 4.414,8.563 8.947,8.625 11.347,8.625 16.147,8.625 17.347,8.625 18.547,8.625 26.947,8.625 28.147,8.625 32.947,8.625 34.147,8.625 0.5,8.708 42.5,8.699 8.395,9.437 4.475,9.684 38.673,9.684 29.947,9.825 31.147,9.825 33.547,9.825 34.747,9.825 42.5,9.926 0.5,9.935 10.147,10.382 13.147,10.801 4.35,10.887 38.757,10.965 8.947,11.025 26.947,11.025 29.347,11.025 32.947,11.025 34.147,11.025 0.5,11.162 42.5,11.153 11.015,11.97 13.351,12.092 38.774,12.176 14.347,12.225 16.747,12.225 17.947,12.225 20.347,12.225 21.547,12.225 27.547,12.225 29.947,12.225 31.147,12.225 33.547,12.225 34.747,12.225 4.35,12.3 0.5,12.389 42.5,12.38 17.306,12.728 21.665,13.049 38.673,13.39 8.947,13.425 10.147,13.425 11.347,13.425 16.147,13.425 18.547,13.425 20.947,13.425 23.347,13.425 4.475,13.557 42.5,13.607 0.5,13.616 17.205,14.116 21.707,14.116 9.547,14.625 10.747,14.625 13.147,14.625 17.947,14.625 20.347,14.625 22.747,14.625 4.35,14.756 38.71,14.738 42.5,14.834 0.5,14.843 23.925,15.316 27.94,15.316 16.566,15.32 17.347,15.825 24.547,15.825 29.347,15.825 30.547,15.825 31.747,15.825 4.428,16.008 38.618,16.008 0.5,16.07 42.5,16.061 13.007,16.4 18.881,16.434 27.96,16.459 20.813,16.469 32.089,16.679 31.147,17.025 4.494,17.257 38.807,17.272 0.5,17.297 24.759,17.297 42.5,17.288 22.642,17.485 19.857,17.524 9.694,17.849 20.947,18.225 22.147,18.225 23.347,18.225 38.757,18.498 42.5,18.515 0.5,18.524 4.475,18.524 10.747,19.425 18.233,19.47 0.5,19.751 38.757,19.746 42.5,19.742 4.475,19.789 21.816,19.911 26.115,20.061 19.688,20.443 22.513,20.496 32.309,20.551 8.947,20.625 10.147,20.625 16.147,20.625 23.347,20.625 0.5,20.978 42.5,20.969 4.35,21.027 26.63,21.15 25.43,21.218 18.787,21.286 10.728,21.333 19.863,21.446 42.5,22.196 0.5,22.205 4.35,22.357 38.71,22.358 19.1,22.8 14.559,22.855 27.332,22.973 8.947,23.025 16.147,23.025 25.156,23.267 12.066,23.343 0.5,23.432 34.519,23.494 22.927,23.532 18.587,23.563 4.35,23.6 9.005,24.176 42.5,24.225 0.5,24.659 27.043,25.034 4.147,25.425 19.428,25.402 42.5,25.877 0.5,25.886 38.801,26.061 11.947,26.625 17.683,26.861 19.698,26.916 0.5,27.113 42.5,27.104 4.35,27.438 21.933,27.44 19.433,27.536 10.147,27.825 11.347,27.825 14.356,27.888 38.801,28.048 0.5,28.34 42.5,28.331 16.929,28.468 10.747,29.025 42.5,29.558 0.5,29.567 4.428,29.978 38.801,29.978 10.147,30.225 11.347,30.225 26.486,30.631 27.96,30.69 42.5,30.785 0.5,30.794 20.757,31.009 30.182,31.031 4.428,31.14 38.673,31.248 20.706,31.771 19.163,31.858 0.5,32.021 42.5,32.012 4.428,32.518 38.757,32.518 20.839,32.58 8.947,32.625 10.147,32.625 28.147,32.625 28.891,33.128 0.5,33.248 42.5,33.239 18.961,33.64 20.706,33.64 4.35,33.788 38.71,33.788 8.347,33.825 10.747,33.825 17.947,33.825 21.547,33.825 22.747,33.825 23.947,33.825 25.147,33.825 26.347,33.825 29.947,33.825 18.917,34.466 42.5,34.466 0.5,34.475 20.777,34.773 1.747,35.025 2.947,35.025 4.147,35.025 5.347,35.025 6.547,35.025 7.747,35.025 8.947,35.025 13.747,35.025 14.947,35.025 16.147,35.025 17.347,35.025 22.147,35.025 23.347,35.025 24.547,35.025 25.747,35.025 26.947,35.025 35.347,35.025 36.547,35.025 37.747,35.025 38.947,35.025 40.147,35.025 41.347,35.025 30.643,35.495 0.5,35.702 32.306,35.693 42.5,35.693 1.147,36.225 2.347,36.225 3.547,36.225 4.747,36.225 5.947,36.225 7.147,36.225 8.347,36.225 9.547,36.225 10.747,36.225 11.947,36.225 13.147,36.225 14.347,36.225 15.547,36.225 16.747,36.225 17.947,36.225 19.147,36.225 21.547,36.225 22.747,36.225 23.947,36.225 25.147,36.225 26.347,36.225 27.547,36.225 28.747,36.225 29.947,36.225 31.147,36.225 33.547,36.225 34.747,36.225 35.947,36.225 37.147,36.225 38.347,36.225 39.547,36.225 40.747,36.225 41.947,36.225 0.5,36.929 32.309,36.92 42.5,36.92 19.047,37.001 21.013,37.028 11.722,37.151 1.747,37.425 2.947,37.425 4.147,37.425 5.347,37.425 6.547,37.425 7.747,37.425 8.947,37.425 10.147,37.425 16.147,37.425 17.347,37.425 22.147,37.425 23.347,37.425 24.547,37.425 25.747,37.425 31.747,37.425 32.947,37.425 34.147,37.425 35.347,37.425 36.547,37.425 37.747,37.425 38.947,37.425 40.147,37.425 41.347,37.425 13.464,37.896 12.378,37.94 14.639,37.96 27.249,37.975 29.416,37.983 28.365,38.003 20.979,38.049 42.5,38.147 0.5,38.156 19.1,38.335 1.147,38.625 2.347,38.625 3.547,38.625 4.747,38.625 5.947,38.625 7.147,38.625 8.347,38.625 9.547,38.625 10.747,38.625 11.947,38.625 15.547,38.625 16.747,38.625 17.947,38.625 22.747,38.625 23.947,38.625 25.147,38.625 26.347,38.625 29.947,38.625 31.147,38.625 32.347,38.625 33.547,38.625 34.747,38.625 35.947,38.625 37.147,38.625 38.347,38.625 39.547,38.625 40.747,38.625 41.947,38.625 20.985,38.884 0.5,39.383 42.5,39.374 19.129,39.74 20.979,39.74 1.747,39.825 2.947,39.825 4.147,39.825 5.347,39.825 6.547,39.825 7.747,39.825 8.947,39.825 10.147,39.825 11.347,39.825 12.547,39.825 13.747,39.825 14.947,39.825 16.147,39.825 17.347,39.825 22.147,39.825 23.347,39.825 24.547,39.825 25.747,39.825 26.947,39.825 28.147,39.825 29.347,39.825 30.547,39.825 31.747,39.825 32.947,39.825 34.147,39.825 35.347,39.825 36.547,39.825 37.747,39.825 38.947,39.825 40.147,39.825 41.347,39.825 0.5,40.61 19.098,40.61 20.979,40.61 42.5,40.601 1.147,41.025 2.347,41.025 3.547,41.025 4.747,41.025 5.947,41.025 7.147,41.025 8.347,41.025 9.547,41.025 10.747,41.025 11.947,41.025 13.147,41.025 14.347,41.025 15.547,41.025 16.747,41.025 17.947,41.025 22.747,41.025 23.947,41.025 25.147,41.025 26.347,41.025 27.547,41.025 28.747,41.025 29.947,41.025 31.147,41.025 32.347,41.025 33.547,41.025 34.747,41.025 35.947,41.025 37.147,41.025 38.347,41.025 39.547,41.025 40.747,41.025 19.098,41.723 42.5,41.828 0.5,41.837 1.747,42.225 2.947,42.225 4.147,42.225 5.347,42.225 6.547,42.225 7.747,42.225 8.947,42.225 10.147,42.225 11.347,42.225 12.547,42.225 13.747,42.225 17.347,42.225 22.147,42.225 26.947,42.225 28.147,42.225 29.347,42.225 30.547,42.225 31.747,42.225 32.947,42.225 34.147,42.225 35.347,42.225 36.547,42.225 37.747,42.225 38.947,42.225 40.147,42.225 41.347,42.225 20.895,42.52 19.098,42.753 0.5,43.064 42.5,43.055 1.147,43.425 8.347,43.425 9.547,43.425 10.747,43.425 11.947,43.425 13.147,43.425 17.947,43.425 22.747,43.425 26.347,43.425 27.547,43.425 28.747,43.425 29.947,43.425 31.147,43.425 32.347,43.425 33.547,43.425 34.747,43.425 35.947,43.425 37.147,43.425 38.347,43.425 39.547,43.425 40.747,43.425 20.895,43.632 19.038,44.11 0.5,44.291 42.5,44.282 1.747,44.625 8.947,44.625 10.147,44.625 11.347,44.625 12.547,44.625 13.747,44.625 17.347,44.625 22.147,44.625 26.947,44.625 28.147,44.625 29.347,44.625 30.547,44.625 31.747,44.625 32.947,44.625 34.147,44.625 35.347,44.625 36.547,44.625 37.747,44.625 38.947,44.625 40.147,44.625 41.347,44.625 20.895,44.663 18.917,45.218 42.5,45.509 0.5,45.518 1.245,46.177 2.161,46.177 3.077,46.177 3.992,46.177 4.908,46.177 5.824,46.177 6.74,46.177 7.656,46.177 8.572,46.177 9.487,46.177 10.403,46.177 11.319,46.177 12.432,46.177 13.529,46.177 14.72,46.177 15.871,46.177 16.954,46.177 17.901,46.177 18.753,46.177 20.879,46.177 21.971,46.177 23.068,46.177 24.181,46.177 25.211,46.177 26.127,46.177 27.043,46.177 27.96,46.177 28.876,46.177 29.792,46.177 30.708,46.177 31.624,46.177 32.54,46.177 33.456,46.177 34.372,46.177 35.288,46.177 36.204,46.177 37.12,46.177 38.036,46.177 38.952,46.177 39.868,46.177 40.784,46.177 41.699,46.177
  other v2: 20.038,28.885
GPIO3/BOOT0: CN1.9 R1.1 U1.G1 | length 24.3
  Top Layer w0.1: R1.1@16.954,31.646 17.049,31.551 17.049,31.265 17.295,31.02 19.021,31.02 U1.G1@19.338,30.703
  Top Layer w0.2: v1(12.878,35.052) 12.878,33.903 13.811,32.97 15.21,32.97 16.429,31.75 16.849,31.75 R1.1@16.954,31.646
  Internal 2 w0.2: v1(8.395,29.57) 8.395,32.881 10.668,35.154 12.561,35.154 12.586,35.129 12.801,35.129 v1(12.878,35.052)
  Bottom Layer w0.2: CN1.9@2.334,28.708 4.35,28.708 4.919,29.277 7.994,29.277 8.287,29.57 v1(8.395,29.57)
GPIO5/JTMS/SWDIO: CN1.13 R2.2 U1.H4 | length 39.7
  Internal 2 w0.1: v1@14.956,25.813 15.382,26.239 15.382,29.999 15.647,30.263 16.051,30.263 16.205,30.109 18.44,30.109 18.618,30.109 18.904,29.823 19.134,29.823 v2(19.163,29.794)
  Internal 2 w0.2: v1(14.908,25.765) 15.64,25.033 16.542,25.033 17.001,24.574 17.001,24.488 17.023,24.467 17.023,18.563 17.901,17.684 17.901,16.179 19.513,14.567 v1(19.513,12.38)
  Bottom Layer w0.2: CN1.13@2.334,26.168 4.35,26.168 4.919,26.737 9.462,26.737 10.434,25.765 v1(14.908,25.765) ; v1(19.513,12.38) 19.513,10.277 R2.2@19.561,10.229
GPIO6/JTCK/SWCLK: CN1.15 R3.2 U1.K2 | length 48.8
  Top Layer w0.1: v1(13.233,32.207) 13.245,32.207 13.557,32.52 14.956,32.52 17.075,30.4 U1.K2@18.813,30.4
  Internal 2 w0.2: v1(13.233,32.207) 13.31,32.131 13.31,31.753 13.461,31.602 13.461,25.118 13.857,24.721 13.857,24.407 14.058,24.206 14.058,23.989 13.857,23.788 13.857,21.903 14.471,21.289 14.471,19.614 v1(14.429,19.571) ; v1(14.681,10.721) 14.691,10.721 15.02,11.05 20.601,11.05 20.723,10.928 v1(20.831,10.928)
  Bottom Layer w0.2: CN1.15@2.334,24.898 4.35,24.898 4.919,25.467 8.719,25.467 10.057,24.128 14.027,24.128 v1(14.058,24.097) ; v1(14.429,19.571) 15.176,18.824 15.176,11.216 v1(14.681,10.721) ; R3.2@20.831,10.23 v1(20.831,10.928)
GPIO12: CN1.26 SB9.1 | length 2.3
  Bottom Layer w0.21: CN1.26@6.398,18.548 7.427,18.548 7.8,18.921 SB9.1@8.538,18.921
GPIO15/OSC32_IN: CN1.33 SB37.2 | length 30.5
  Internal 2 w0.2: v1(12.368,31.228) 12.861,30.736 12.861,24.682 13.257,24.286 13.257,21.63 13.593,21.294 v1(13.593,20.212)
  Bottom Layer w0.2: CN1.33@2.334,13.468 3.363,13.468 3.774,13.057 4.761,13.057 4.919,12.9 12.883,12.9 13.709,13.726 13.709,17.257 12.988,17.979 12.988,19.607 v1(13.593,20.212)
GPIO16/OSC32_OUT: CN1.35 SB38.2 | length 28.8
  Internal 2 w0.2: v1(12.255,28.816) 12.255,28.804 12.561,28.498 12.561,24.465 12.957,24.068 12.957,19.965 13.593,19.329 v1(13.593,18.378)
  Bottom Layer w0.2: CN1.35@2.334,12.198 3.363,12.198 3.631,11.93 3.631,11.747 3.749,11.63 7.878,11.63 8.848,12.6 13.008,12.6 14.009,13.601 14.009,17.382 13.593,17.797 v1(13.593,18.378)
